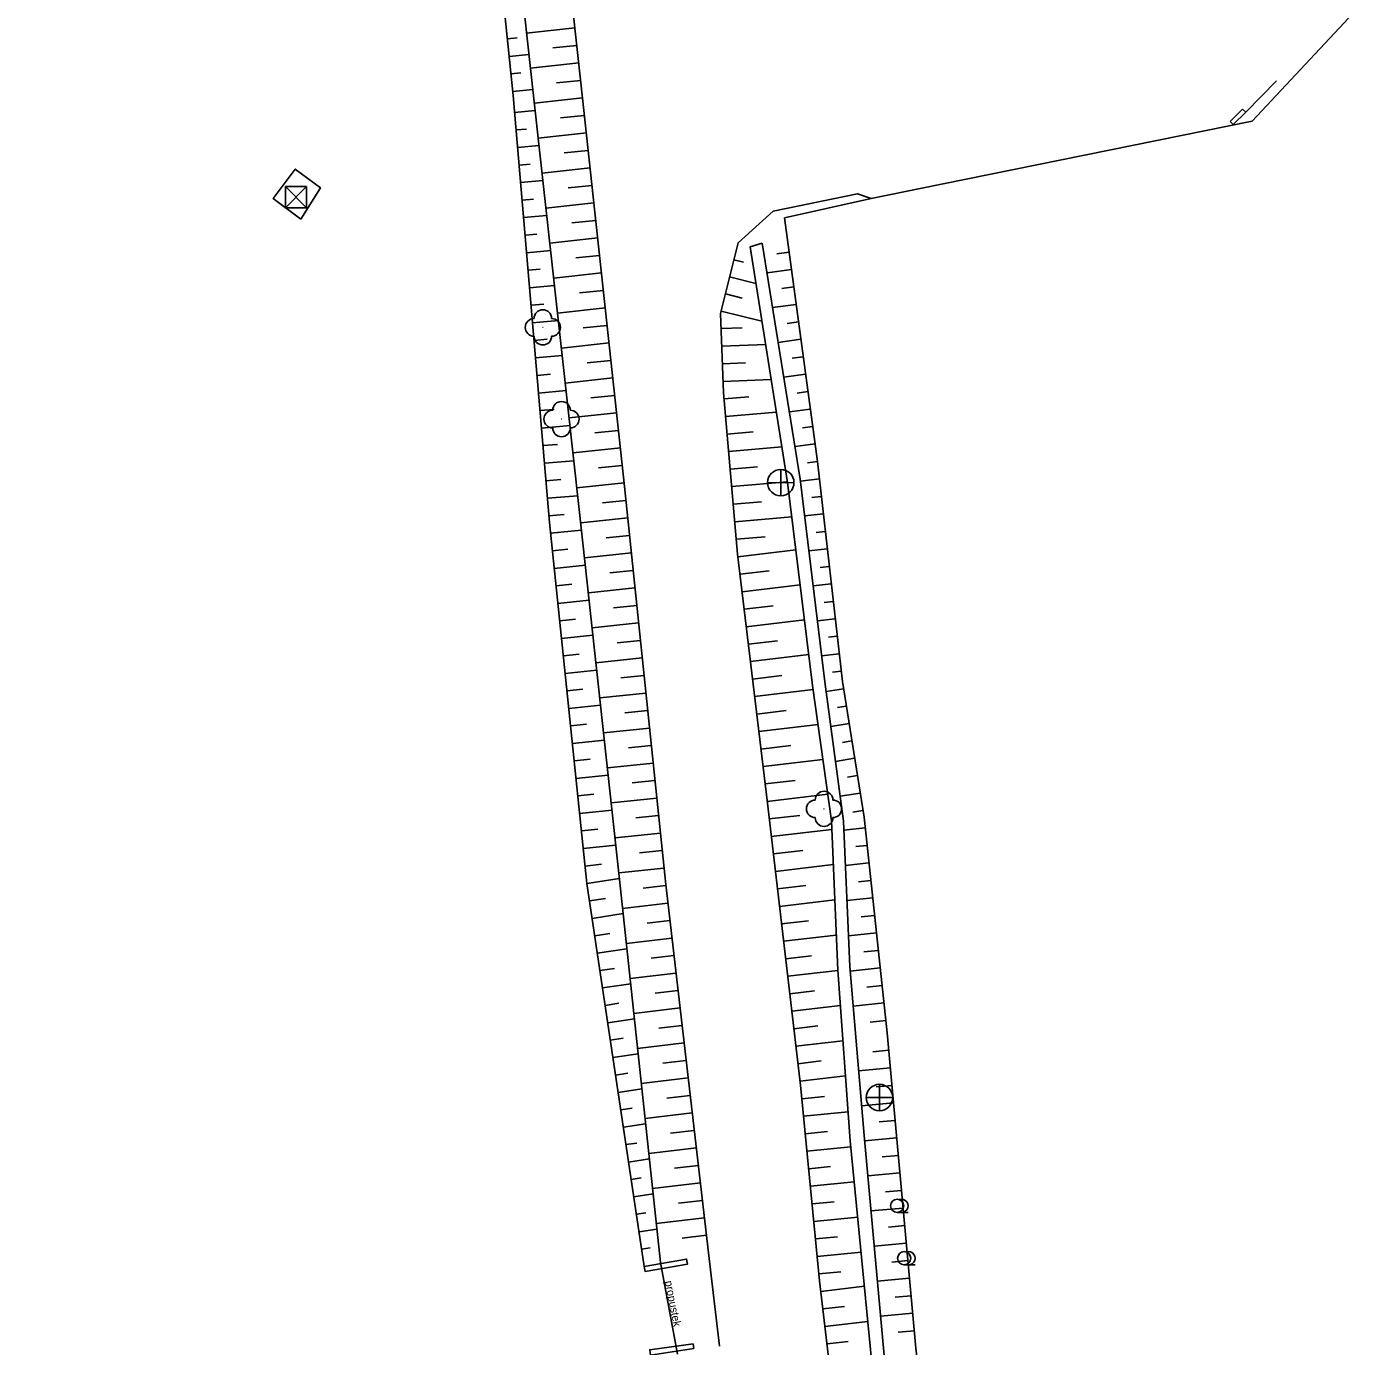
# Model space of a CAD drawing. Extents: x -747135 to -746147, y -1093269 to -1091735.
# Drawn here: x -746679 to -746602.5, y -1092733.1 to -1092658.1 of the extents above; entities that cross this region are included whole.
import ezdxf

# ---------------------------------------------------------------- set-up
doc = ezdxf.new("R2010")
doc.units = 0
for name, color, linetype in [('101', 7, 'Continuous'), ('1016', 7, 'Continuous'), ('1029', 7, 'Continuous'), ('105', 7, 'Continuous'), ('23700', 7, 'Continuous'), ('305', 7, 'Continuous'), ('306', 7, 'Continuous'), ('316', 7, 'Continuous'), ('424', 7, 'Continuous'), ('803', 7, 'Continuous')]:
    doc.layers.add(name, color=color, linetype=linetype)

msp = doc.modelspace()

# ---------------------------------------------------------------- linework, layer by layer
at = {"layer": '101'}
for points in [[(-746643.03, -1092728.31), (-746645.35, -1092706.55), (-746647.64, -1092685.53), (-746650.22, -1092662.21), (-746652.01, -1092645.97), (-746654.41, -1092623.21), (-746657.16, -1092600.72), (-746657.52, -1092586.28), (-746659.03, -1092575.98), (-746661.36, -1092561.58), (-746663.99, -1092551.17), (-746668.72, -1092536.82), (-746673.6, -1092526.76), (-746679.03, -1092516.89)], [(-746647.886, -1092658.174), (-746650.632, -1092658.474)], [(-746651.73, -1092658.802), (-746651.169, -1092658.744)], [(-746647.778, -1092659.168), (-746649.15, -1092659.318)], [(-746651.628, -1092659.797), (-746650.499, -1092659.681)], [(-746647.669, -1092660.163), (-746650.413, -1092660.462)], [(-746651.526, -1092660.791), (-746650.958, -1092660.733)], [(-746651.424, -1092661.786), (-746650.28, -1092661.669)], [(-746647.561, -1092661.157), (-746648.932, -1092661.306)], [(-746643.95, -1092728.54), (-746647.21, -1092706.78), (-746649.33, -1092686.28), (-746651.4, -1092662.02)], [(-746647.452, -1092662.151), (-746650.193, -1092662.45)], [(-746651.318, -1092662.977), (-746650.146, -1092662.877)], [(-746647.345, -1092663.145), (-746648.714, -1092663.293)], [(-746651.233, -1092663.973), (-746650.635, -1092663.922)], [(-746647.238, -1092664.139), (-746649.974, -1092664.434)], [(-746651.148, -1092664.97), (-746649.926, -1092664.865)], [(-746647.13, -1092665.133), (-746648.497, -1092665.281)], [(-746651.063, -1092665.966), (-746650.44, -1092665.913)], [(-746647.023, -1092666.128), (-746649.754, -1092666.422)], [(-746650.978, -1092666.962), (-746649.706, -1092666.854)], [(-746646.916, -1092667.122), (-746648.28, -1092667.269)], [(-746650.893, -1092667.959), (-746650.245, -1092667.903)], [(-746646.808, -1092668.116), (-746649.534, -1092668.41)], [(-746650.808, -1092668.955), (-746649.486, -1092668.842)], [(-746646.701, -1092669.11), (-746648.063, -1092669.257)], [(-746650.723, -1092669.952), (-746650.05, -1092669.894)], [(-746646.594, -1092670.105), (-746649.314, -1092670.398)], [(-746650.638, -1092670.948), (-746649.266, -1092670.831)], [(-746637.93, -1092670.61), (-746637.24, -1092670.41)], [(-746627.38, -1092772.91), (-746628.52, -1092760.62), (-746630.29, -1092741.41), (-746632.24, -1092721.4), (-746632.95, -1092711.71), (-746633.31, -1092703.22), (-746634.38, -1092695.54), (-746635.8, -1092684.01), (-746637.93, -1092670.61)], [(-746637.24, -1092670.41), (-746635.08, -1092683.82), (-746633.69, -1092695.33), (-746632.62, -1092703.25), (-746632.27, -1092711.5), (-746631.46, -1092721.1), (-746629.61, -1092741.3), (-746627.76, -1092760.57), (-746626.45, -1092772.93)], [(-746635.709, -1092670.911), (-746636.419, -1092671.006)], [(-746646.487, -1092671.099), (-746647.845, -1092671.245)], [(-746638.859, -1092671.351), (-746638.314, -1092671.485)], [(-746650.553, -1092671.944), (-746649.855, -1092671.885)], [(-746646.379, -1092672.093), (-746649.094, -1092672.386)], [(-746639.098, -1092672.322), (-746637.599, -1092672.691)], [(-746635.576, -1092671.902), (-746636.969, -1092672.089)], [(-746650.468, -1092672.941), (-746649.046, -1092672.819)], [(-746646.272, -1092673.087), (-746647.628, -1092673.234)], [(-746635.443, -1092672.893), (-746636.127, -1092672.985)], [(-746650.383, -1092673.937), (-746649.66, -1092673.875)], [(-746639.337, -1092673.293), (-746638.383, -1092673.528)], [(-746635.31, -1092673.884), (-746636.651, -1092674.065)], [(-746646.165, -1092674.081), (-746648.874, -1092674.374)], [(-746639.576, -1092674.264), (-746637.258, -1092674.835)], [(-746650.298, -1092674.933), (-746648.826, -1092674.808)], [(-746646.058, -1092675.076), (-746647.411, -1092675.222)], [(-746639.578, -1092675.259), (-746638.391, -1092675.215)], [(-746635.176, -1092674.875), (-746635.834, -1092674.964)], [(-746650.213, -1092675.93), (-746649.465, -1092675.866)], [(-746645.95, -1092676.07), (-746648.654, -1092676.362)], [(-746639.54, -1092676.259), (-746637.047, -1092676.165)], [(-746635.043, -1092675.867), (-746636.333, -1092676.04)], [(-746650.128, -1092676.926), (-746648.606, -1092676.796)], [(-746634.91, -1092676.858), (-746635.542, -1092676.943)], [(-746645.843, -1092677.064), (-746647.194, -1092677.21)], [(-746639.502, -1092677.258), (-746638.196, -1092677.209)], [(-746650.043, -1092677.923), (-746649.27, -1092677.857)], [(-746645.736, -1092678.058), (-746648.434, -1092678.35)], [(-746639.465, -1092678.257), (-746636.731, -1092678.154)], [(-746634.777, -1092677.849), (-746636.015, -1092678.015)], [(-746649.958, -1092678.919), (-746648.386, -1092678.785)], [(-746645.629, -1092679.053), (-746646.977, -1092679.198)], [(-746639.41, -1092679.255), (-746638.002, -1092679.133)], [(-746634.644, -1092678.84), (-746635.25, -1092678.921)], [(-746649.873, -1092679.915), (-746649.075, -1092679.847)], [(-746645.521, -1092680.047), (-746648.214, -1092680.337)], [(-746639.323, -1092680.252), (-746636.437, -1092680)], [(-746634.51, -1092679.831), (-746635.697, -1092679.99)], [(-746649.788, -1092680.912), (-746648.166, -1092680.773)], [(-746634.377, -1092680.822), (-746634.957, -1092680.9)], [(-746645.414, -1092681.041), (-746646.759, -1092681.186)], [(-746639.236, -1092681.248), (-746637.758, -1092681.119)], [(-746649.703, -1092681.908), (-746648.88, -1092681.838)], [(-746645.307, -1092682.035), (-746647.995, -1092682.325)], [(-746639.149, -1092682.244), (-746636.123, -1092681.98)], [(-746634.244, -1092681.813), (-746635.379, -1092681.966)], [(-746649.618, -1092682.904), (-746647.946, -1092682.762)], [(-746645.2, -1092683.03), (-746646.542, -1092683.174)], [(-746639.062, -1092683.24), (-746637.514, -1092683.105)], [(-746634.111, -1092682.804), (-746634.665, -1092682.879)], [(-746649.533, -1092683.901), (-746648.685, -1092683.828)], [(-746633.998, -1092683.798), (-746635.068, -1092683.919)], [(-746645.092, -1092684.024), (-746647.775, -1092684.313)], [(-746638.975, -1092684.236), (-746635.808, -1092683.96)], [(-746649.448, -1092684.897), (-746647.726, -1092684.75)], [(-746644.988, -1092685.018), (-746646.327, -1092685.157)], [(-746638.888, -1092685.233), (-746637.286, -1092685.093)], [(-746633.885, -1092684.791), (-746634.417, -1092684.852)], [(-746649.363, -1092685.894), (-746648.49, -1092685.819)], [(-746644.885, -1092686.013), (-746647.557, -1092686.29)], [(-746638.801, -1092686.229), (-746635.562, -1092685.946)], [(-746633.772, -1092685.785), (-746634.828, -1092685.905)], [(-746649.267, -1092686.889), (-746647.512, -1092686.707)], [(-746633.659, -1092686.779), (-746634.184, -1092686.838)], [(-746644.783, -1092687.008), (-746646.116, -1092687.146)], [(-746638.715, -1092687.225), (-746637.077, -1092687.082)], [(-746649.164, -1092687.884), (-746648.284, -1092687.793)], [(-746644.68, -1092688.002), (-746647.341, -1092688.278)], [(-746638.623, -1092688.221), (-746635.33, -1092687.827)], [(-746633.546, -1092687.772), (-746634.588, -1092687.891)], [(-746649.061, -1092688.878), (-746647.295, -1092688.696)], [(-746644.577, -1092688.997), (-746645.904, -1092689.135)], [(-746638.504, -1092689.214), (-746636.856, -1092689.017)], [(-746633.433, -1092688.766), (-746633.951, -1092688.825)], [(-746648.958, -1092689.873), (-746648.073, -1092689.781)], [(-746644.474, -1092689.992), (-746647.124, -1092690.266)], [(-746638.386, -1092690.207), (-746635.085, -1092689.812)], [(-746633.321, -1092689.759), (-746634.349, -1092689.876)], [(-746648.856, -1092690.868), (-746647.079, -1092690.684)], [(-746633.208, -1092690.753), (-746633.718, -1092690.811)], [(-746644.371, -1092690.986), (-746645.693, -1092691.123)], [(-746638.267, -1092691.2), (-746636.615, -1092691.002)], [(-746648.753, -1092691.862), (-746647.861, -1092691.77)], [(-746644.268, -1092691.981), (-746646.907, -1092692.254)], [(-746638.148, -1092692.193), (-746634.841, -1092691.797)], [(-746633.095, -1092691.747), (-746634.109, -1092691.862)], [(-746648.65, -1092692.857), (-746646.862, -1092692.672)], [(-746644.165, -1092692.976), (-746645.482, -1092693.112)], [(-746638.03, -1092693.186), (-746636.374, -1092692.988)], [(-746632.982, -1092692.74), (-746633.485, -1092692.797)], [(-746648.547, -1092693.852), (-746647.65, -1092693.759)], [(-746637.911, -1092694.178), (-746634.596, -1092693.782)], [(-746632.869, -1092693.734), (-746633.869, -1092693.847)], [(-746644.062, -1092693.971), (-746646.691, -1092694.243)], [(-746648.444, -1092694.846), (-746646.645, -1092694.66)], [(-746643.959, -1092694.965), (-746645.271, -1092695.101)], [(-746637.792, -1092695.171), (-746636.133, -1092694.973)], [(-746632.756, -1092694.727), (-746633.253, -1092694.784)], [(-746648.341, -1092695.841), (-746647.439, -1092695.748)], [(-746643.856, -1092695.96), (-746646.474, -1092696.231)], [(-746637.674, -1092696.164), (-746634.348, -1092695.767)], [(-746632.625, -1092695.719), (-746633.616, -1092695.877)], [(-746648.238, -1092696.836), (-746646.429, -1092696.649)], [(-746632.467, -1092696.706), (-746632.975, -1092696.787)], [(-746643.753, -1092696.955), (-746645.059, -1092697.09)], [(-746637.555, -1092697.157), (-746635.883, -1092696.957)], [(-746632.309, -1092697.693), (-746633.348, -1092697.859)], [(-746648.136, -1092697.831), (-746647.228, -1092697.737)], [(-746643.65, -1092697.949), (-746646.258, -1092698.219)], [(-746637.436, -1092698.15), (-746634.072, -1092697.748)], [(-746648.033, -1092698.825), (-746646.212, -1092698.637)], [(-746643.547, -1092698.944), (-746644.848, -1092699.079)], [(-746637.318, -1092699.143), (-746635.626, -1092698.941)], [(-746632.152, -1092698.681), (-746632.683, -1092698.766)], [(-746647.93, -1092699.82), (-746647.017, -1092699.726)], [(-746643.444, -1092699.939), (-746646.041, -1092700.207)], [(-746637.199, -1092700.136), (-746633.796, -1092699.729)], [(-746631.994, -1092699.668), (-746633.08, -1092699.842)], [(-746647.827, -1092700.815), (-746645.995, -1092700.625)], [(-746631.836, -1092700.656), (-746632.391, -1092700.745)], [(-746643.341, -1092700.933), (-746644.637, -1092701.067)], [(-746637.08, -1092701.129), (-746635.369, -1092700.924)], [(-746647.724, -1092701.809), (-746646.806, -1092701.714)], [(-746643.238, -1092701.928), (-746645.824, -1092702.196)], [(-746636.962, -1092702.122), (-746633.52, -1092701.711)], [(-746631.678, -1092701.643), (-746632.813, -1092701.825)], [(-746647.621, -1092702.804), (-746645.779, -1092702.614)], [(-746643.135, -1092702.923), (-746644.426, -1092703.056)], [(-746636.845, -1092703.115), (-746635.113, -1092702.912)], [(-746631.521, -1092702.631), (-746632.1, -1092702.723)], [(-746647.518, -1092703.799), (-746646.594, -1092703.703)], [(-746636.728, -1092704.108), (-746633.289, -1092703.705)], [(-746631.394, -1092703.623), (-746632.599, -1092703.752)], [(-746643.032, -1092703.917), (-746645.608, -1092704.184)], [(-746647.415, -1092704.793), (-746645.562, -1092704.602)], [(-746642.93, -1092704.912), (-746644.214, -1092705.045)], [(-746636.612, -1092705.101), (-746634.929, -1092704.904)], [(-746631.287, -1092704.617), (-746631.922, -1092704.685)], [(-746647.313, -1092705.788), (-746646.383, -1092705.692)], [(-746642.827, -1092705.907), (-746645.391, -1092706.172)], [(-746636.495, -1092706.095), (-746633.204, -1092705.708)], [(-746631.18, -1092705.611), (-746632.514, -1092705.755)], [(-746647.21, -1092706.783), (-746645.355, -1092706.505)], [(-746631.073, -1092706.605), (-746631.772, -1092706.681)], [(-746647.061, -1092707.772), (-746646.155, -1092707.636)], [(-746642.723, -1092706.901), (-746644.002, -1092707.05)], [(-746636.379, -1092707.088), (-746634.77, -1092706.899)], [(-746630.965, -1092707.6), (-746632.429, -1092707.757)], [(-746642.607, -1092707.895), (-746645.175, -1092708.194)], [(-746636.262, -1092708.081), (-746633.12, -1092707.712)], [(-746646.913, -1092708.761), (-746645.143, -1092708.495)], [(-746642.491, -1092708.888), (-746643.78, -1092709.038)], [(-746636.146, -1092709.074), (-746634.611, -1092708.894)], [(-746630.858, -1092708.594), (-746631.622, -1092708.676)], [(-746646.765, -1092709.75), (-746645.901, -1092709.62)], [(-746642.376, -1092709.881), (-746644.963, -1092710.183)], [(-746636.029, -1092710.067), (-746633.035, -1092709.716)], [(-746630.751, -1092709.588), (-746632.344, -1092709.76)], [(-746646.617, -1092710.739), (-746644.93, -1092710.486)], [(-746630.644, -1092710.582), (-746631.473, -1092710.672)], [(-746642.26, -1092710.875), (-746643.558, -1092711.026)], [(-746635.913, -1092711.061), (-746634.452, -1092710.889)], [(-746646.469, -1092711.728), (-746645.647, -1092711.604)], [(-746642.144, -1092711.868), (-746644.751, -1092712.171)], [(-746635.796, -1092712.054), (-746632.949, -1092711.72)], [(-746630.537, -1092711.576), (-746632.248, -1092711.761)], [(-746646.321, -1092712.717), (-746644.718, -1092712.477)], [(-746642.029, -1092712.861), (-746643.337, -1092713.013)], [(-746635.679, -1092713.047), (-746634.278, -1092712.882)], [(-746630.43, -1092712.571), (-746631.297, -1092712.664)], [(-746646.172, -1092713.706), (-746645.392, -1092713.589)], [(-746635.563, -1092714.04), (-746632.803, -1092713.716)], [(-746630.323, -1092713.565), (-746632.08, -1092713.754)], [(-746646.024, -1092714.695), (-746644.506, -1092714.467)], [(-746641.913, -1092713.854), (-746644.539, -1092714.16)], [(-746641.797, -1092714.848), (-746643.115, -1092715.001)], [(-746635.446, -1092715.033), (-746634.088, -1092714.874)], [(-746630.216, -1092714.559), (-746631.106, -1092714.655)], [(-746645.876, -1092715.683), (-746645.138, -1092715.573)], [(-746641.682, -1092715.841), (-746644.327, -1092716.149)], [(-746635.33, -1092716.026), (-746632.657, -1092715.713)], [(-746645.728, -1092716.672), (-746644.294, -1092716.458)], [(-746630.049, -1092716.256), (-746630.952, -1092716.338)], [(-746645.58, -1092717.661), (-746644.884, -1092717.557)], [(-746641.566, -1092716.834), (-746642.893, -1092716.989)], [(-746635.213, -1092717.02), (-746633.898, -1092716.865)], [(-746629.959, -1092717.252), (-746631.771, -1092717.417)], [(-746641.45, -1092717.828), (-746644.115, -1092718.138)], [(-746635.097, -1092718.013), (-746632.51, -1092717.709)], [(-746629.868, -1092718.248), (-746630.777, -1092718.33)], [(-746645.432, -1092718.65), (-746644.081, -1092718.448)], [(-746641.335, -1092718.821), (-746642.672, -1092718.977)], [(-746634.995, -1092719.008), (-746633.714, -1092718.882)], [(-746645.283, -1092719.639), (-746644.629, -1092719.541)], [(-746641.219, -1092719.814), (-746643.902, -1092720.127)], [(-746634.897, -1092720.003), (-746632.361, -1092719.754)], [(-746629.777, -1092719.244), (-746631.603, -1092719.41)], [(-746645.135, -1092720.628), (-746643.869, -1092720.439)], [(-746629.687, -1092720.239), (-746630.603, -1092720.323)], [(-746641.103, -1092720.807), (-746642.45, -1092720.964)], [(-746634.799, -1092720.998), (-746633.543, -1092720.875)], [(-746629.596, -1092721.235), (-746631.432, -1092721.402)], [(-746644.987, -1092721.617), (-746644.375, -1092721.526)], [(-746640.988, -1092721.801), (-746643.69, -1092722.115)], [(-746634.702, -1092721.993), (-746632.206, -1092721.748)], [(-746644.839, -1092722.606), (-746643.657, -1092722.429)], [(-746640.872, -1092722.794), (-746642.228, -1092722.952)], [(-746634.604, -1092722.988), (-746633.357, -1092722.866)], [(-746629.506, -1092722.231), (-746630.423, -1092722.315)], [(-746644.691, -1092723.595), (-746644.121, -1092723.51)], [(-746629.415, -1092723.227), (-746631.25, -1092723.394)], [(-746644.543, -1092724.584), (-746643.445, -1092724.42)], [(-746640.756, -1092723.787), (-746643.478, -1092724.104)], [(-746634.506, -1092723.984), (-746632.012, -1092723.739)], [(-746629.324, -1092724.223), (-746630.241, -1092724.306)], [(-746640.64, -1092724.781), (-746642.006, -1092724.94)], [(-746634.409, -1092724.979), (-746633.162, -1092724.857)], [(-746629.234, -1092725.219), (-746631.067, -1092725.386)], [(-746644.394, -1092725.573), (-746643.867, -1092725.494)], [(-746640.525, -1092725.774), (-746643.266, -1092726.093)], [(-746634.311, -1092725.974), (-746631.818, -1092725.73)], [(-746644.246, -1092726.562), (-746643.233, -1092726.41)], [(-746629.143, -1092726.215), (-746630.06, -1092726.298)], [(-746644.098, -1092727.551), (-746643.612, -1092727.478)], [(-746640.409, -1092726.767), (-746641.785, -1092726.927)], [(-746634.214, -1092726.969), (-746632.967, -1092726.847)], [(-746629.052, -1092727.211), (-746630.885, -1092727.377)], [(-746634.116, -1092727.965), (-746631.624, -1092727.72)], [(-746628.962, -1092728.206), (-746629.878, -1092728.29)], [(-746634.018, -1092728.96), (-746632.773, -1092728.838)], [(-746633.909, -1092729.954), (-746631.435, -1092729.664)], [(-746628.871, -1092729.202), (-746630.703, -1092729.369)], [(-746628.78, -1092730.198), (-746629.696, -1092730.282)], [(-746633.793, -1092730.947), (-746632.565, -1092730.803)], [(-746628.69, -1092731.194), (-746630.52, -1092731.361)], [(-746633.677, -1092731.94), (-746631.241, -1092731.655)], [(-746633.561, -1092732.934), (-746632.352, -1092732.792)], [(-746628.599, -1092732.19), (-746629.514, -1092732.273)]]:
    msp.add_lwpolyline(points, dxfattribs=at)
at = {"layer": '1016'}
for points in [[(-746640.293, -1092727.76), (-746642.73, -1092706.84), (-746645.07, -1092684.23), (-746647.45, -1092662.17), (-746649.23, -1092645.87), (-746651.64, -1092623.4), (-746654, -1092600.5), (-746655.65, -1092585.38), (-746656.67, -1092576.42), (-746659.12, -1092561.65), (-746661.88, -1092550.86), (-746667.11, -1092535.97), (-746671.93, -1092526), (-746677.329, -1092516.06)], [(-746663.46, -1092669.04), (-746662.35, -1092667.27), (-746663.78, -1092666.2), (-746665.032, -1092667.872), (-746663.46, -1092669.04)], [(-746631.05, -1092667.87), (-746631.83, -1092667.6), (-746636.63, -1092668.59), (-746638.62, -1092670.38)], [(-746638.62, -1092670.38), (-746639.61, -1092674.4), (-746639.44, -1092678.91), (-746638.64, -1092688.08), (-746636.95, -1092702.22), (-746635.07, -1092718.24), (-746633.98, -1092729.35), (-746632.34, -1092743.37), (-746630.46, -1092760.33), (-746628.78, -1092773.02)], [(-746643.95, -1092728.54), (-746641.54, -1092728.12), (-746641.491, -1092728.416), (-746643.897, -1092728.82), (-746643.95, -1092728.54)], [(-746639.676, -1092733.059), (-746640.293, -1092727.763)], [(-746641.13, -1092733.2), (-746643.6, -1092733.57), (-746643.64, -1092733.273), (-746641.172, -1092732.94), (-746641.13, -1092733.2)]]:
    msp.add_lwpolyline(points, dxfattribs=at)
at = {"layer": '1029'}
for p, q in [((-746629.58, -1092725.465), (-746628.955, -1092725.465)), ((-746629.18, -1092728.445), (-746628.555, -1092728.445))]:
    msp.add_line(p, q, dxfattribs=at)
for centre in [(-746629.58, -1092725.09), (-746629.18, -1092728.07)]:
    msp.add_circle(centre, 0.375, dxfattribs=at)
for centre in [(-746629.33, -1092725.09), (-746628.93, -1092728.07)]:
    msp.add_arc(centre, 0.375, 249.49437, 109.04743, dxfattribs=at)
at = {"layer": '23700'}
msp.add_lwpolyline([(-746642.05, -1092733.51), (-746643.03, -1092728.31)], dxfattribs=at)
at = {"layer": '305'}
for points in [[(-746602.53, -1092656.1), (-746609.4, -1092663.48)], [(-746627.05, -1092667.06), (-746631.05, -1092667.87)]]:
    msp.add_lwpolyline(points, dxfattribs=at)
at = {"layer": '306'}
for p, q in [((-746609.77, -1092662.96), (-746608.016, -1092661.179)), ((-746609.948, -1092662.785), (-746610.65, -1092663.497)), ((-746610.472, -1092663.672), (-746609.77, -1092662.96)), ((-746609.77, -1092662.96), (-746609.948, -1092662.785)), ((-746610.65, -1092663.497), (-746610.472, -1092663.672))]:
    msp.add_line(p, q, dxfattribs=at)
at = {"layer": '316'}
for p, q in [((-746664.34, -1092667.19), (-746663.14, -1092668.39)), ((-746663.14, -1092667.19), (-746664.34, -1092668.39)), ((-746663.14, -1092667.19), (-746664.34, -1092667.19)), ((-746664.34, -1092667.19), (-746664.34, -1092668.39)), ((-746663.14, -1092668.39), (-746663.14, -1092667.19)), ((-746664.34, -1092668.39), (-746663.14, -1092668.39)), ((-746636.191, -1092684.758), (-746636.19, -1092683.263)), ((-746635.438, -1092684.016), (-746636.938, -1092684.011)), ((-746630.581, -1092719.688), (-746630.58, -1092718.193)), ((-746629.828, -1092718.946), (-746631.328, -1092718.941))]:
    msp.add_line(p, q, dxfattribs=at)
for centre in [(-746636.19, -1092684.01), (-746630.58, -1092718.94)]:
    msp.add_circle(centre, 0.75, dxfattribs=at)
at = {"layer": '424'}
msp.add_lwpolyline([(-746666.44, -1092549), (-746665.36, -1092551.34), (-746663.2, -1092562.01), (-746660.43, -1092576.24), (-746658.93, -1092586.95), (-746657.16, -1092600.72), (-746656.07, -1092616.52), (-746651.4, -1092662.02)], dxfattribs=at)
for centre in [(-746649.71, -1092675.19), (-746648.65, -1092680.4), (-746633.73, -1092702.54)]:
    msp.add_circle(centre, 0.0005, dxfattribs=at)
for centre, start, end in [((-746650.21, -1092675.19), 89.99999, 269.99999), ((-746649.71, -1092674.69), 0, 179.99999), ((-746649.21, -1092675.19), 270, 89.99999), ((-746649.71, -1092675.69), 179.99999, 359.99999), ((-746649.15, -1092680.4), 89.99999, 269.99999), ((-746648.65, -1092679.9), 0, 179.99999), ((-746648.15, -1092680.4), 270, 89.99999), ((-746648.65, -1092680.9), 179.99999, 359.99999), ((-746634.23, -1092702.54), 89.99999, 269.99999), ((-746633.73, -1092702.04), 0, 179.99999), ((-746633.23, -1092702.54), 270, 89.99999), ((-746633.73, -1092703.04), 179.99999, 359.99999)]:
    msp.add_arc(centre, 0.5, start, end, dxfattribs=at)
at = {"layer": '803'}
for points in [[(-746609.4, -1092663.48), (-746627.05, -1092667.06)], [(-746631.05, -1092667.87), (-746635.97, -1092668.97), (-746634.11, -1092682.81), (-746632.69, -1092695.31), (-746631.46, -1092703.01), (-746630.14, -1092715.26)], [(-746630.14, -1092715.26), (-746628.51, -1092733.17), (-746628.35, -1092734.6), (-746626.39, -1092754.68)]]:
    msp.add_lwpolyline(points, dxfattribs=at)

# ---------------------------------------------------------------- texts
at = {"layer": '105'}
msp.add_text('propustek', height=0.45, rotation=280.88069, dxfattribs=at).set_placement((-746642.779, -1092729.387))

doc.saveas('drawing.dxf')
